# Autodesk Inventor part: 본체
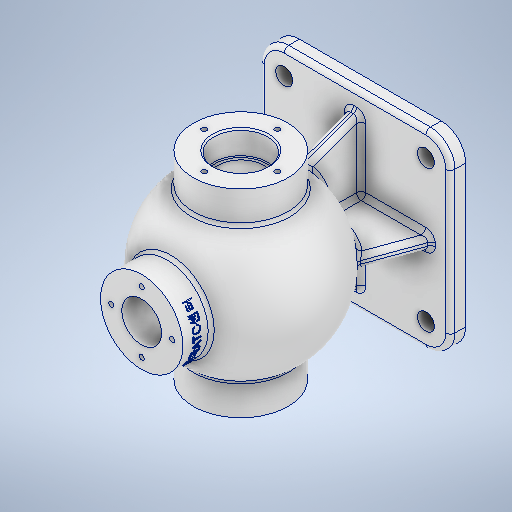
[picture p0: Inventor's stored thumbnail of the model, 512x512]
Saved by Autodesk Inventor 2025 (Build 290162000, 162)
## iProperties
Created: 2025-08
Part Number: 본체
Material: 알루미늄 6061
Document SubType Name: Modeling
Designer: infra028
Density: 2.7 g/cm^3
Appearance: 알루미늄 - 평지
Mass: 1526.56 g
Surface Area: 1173.66 cm^2
Volume: 565.392 cm^3
Author: infra028
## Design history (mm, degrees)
sketch "스케치1"
  geometry: L1 (-62.5, 62.5)-(62.5, 62.5); L2 (62.5, 62.5)-(62.5, -62.5); L3 (62.5, -62.5)-(-62.5, -62.5); L4 (-62.5, -62.5)-(-62.5, 62.5); L5 (-62.5, 62.5)-(62.5, -62.5); L6 (62.5, 62.5)-(-62.5, -62.5); 1 further point
  constraints: 12 end point, 2 midpoint, 2 parallel, 1 horizontal, 1 perpendicular
  dimensions: "d0" = 125 distance of L2.end L3.end; "d1" = 125 distance of L1.end L2.end
extrude "돌출1" new body sketch "스케치1" distance "d2" = 10; taper "d3" = 0 deg
sketch "스케치2"
  geometry: L1 (-46.5, 46.5)-(46.5, 46.5); L2 (46.5, 46.5)-(46.5, -46.5); L3 (46.5, -46.5)-(-46.5, -46.5); L4 (-46.5, -46.5)-(-46.5, 46.5); L5 (62.5, -62.5)-(62.5, 62.5) reference; L6 (-62.5, 62.5)-(-62.5, -62.5) reference; L7 (62.5, 62.5)-(-62.5, 62.5) reference; L8 (-62.5, -62.5)-(62.5, -62.5) reference; 5 further points
  constraints: 8 end point, 4 coincident, 2 parallel, 1 horizontal, 1 perpendicular
  dimensions: "d4" = 93 distance of L2.end L3.end; "d5" = 93 distance of L1.end L2.end; "d6" = 16 distance between parallel lines of L5 L2 (= d7); "d7" = 16 distance between parallel lines of L4 L6 (derived); "d8" = 16 distance between parallel lines of L1 L7 (= d9); "d9" = 16 distance between parallel lines of L8 L3 (derived)
hole "구멍1" sketch "스케치2" at (46.5, 46.5), (-46.5, -46.5), (46.5, -46.5), (-46.5, 46.5) diameter "d10" = 11; stored, may be unused: countersink angle "d14" = 90 deg, drill point angle "d16" = 0 deg; dims "d11" = 8, "d12" = 4, "d13" = 2, "d15" = 11.8
sketch "스케치4"
  geometry: L1 (54, 85)-(-54, 85); L2 (62.5, 0)-(-62.5, 0) reference; L3 (62.5, 0)-(62.5, 10) reference; A1 r 54 centre (0, 85) between (54, 85) and (-54, 85); 3 further points
  constraints: 2 end point, 2 midpoint, 2 point on circle, 1 centre point, 1 horizontal
  dimensions: "d18" = 108 diameter of A1; "d20" = 85 distance from line of L2 point (0, 85); "d21" = 62.5 horizontal distance of A1.centre point (62.5, 5); "d22" = 8.5 distance from line of L1.start L3
revolve "회전1" sketch "스케치4" stored, may be unused: angle "d19" = 360 deg
sketch "스케치5"
  geometry: L1 (-62.5, 10)-(62.5, 10) reference; L2 (-34.447, 54.104)-(-50.5, 10); L3 (43.084, 10)-(-50.5, 10); L4 (62.5, 0)-(62.5, 10) reference; L5 (-62.5, 0)-(-62.5, 10) reference; L6 (50.5, 10)-(34.447, 54.104); L7 (34.447, 54.104)-(-34.447, 54.104); 1 further point
  constraints: 8 end point, 3 point on line, 1 horizontal
  dimensions: "d24" = 20 deg angle of L2 L5; "d25" = 20 deg angle of L4 L6; "d26" = 12 distance from line of L6.start L4; "d27" = 12 distance of L1.start L2.end; "d28" = 44.10432 distance between parallel lines of L1 L7
extrude "돌출2" join sketch "스케치5" stored distance "d29" = 8; taper "d30" = 0 deg
sketch "스케치6"
  geometry: L1 (50.5, 10)-(33.738, 56.054); L2 (62.5, 0)-(62.5, 10) reference; L3 (-62.5, 10)-(62.5, 10) reference; L4 (-50.5, 10)-(-33.738, 56.054); L5 (-62.5, 0)-(-62.5, 10) reference; L6 (33.738, 56.054)-(-33.738, 56.054); 1 further point
  constraints: 6 end point, 2 point on line, 1 horizontal
  dimensions: "d31" = 20 deg angle of L2 L1; "d32" = 12 distance of L2.end L1.start; "d33" = 20 deg angle of L5 L4; "d34" = 12 distance of L3.start L4.start; "d35" = 46.0543 distance between parallel lines of L3 L6
extrude "돌출3" join sketch "스케치6" stored distance "d36" = 8; taper "d37" = 0 deg
sketch "스케치7"
  geometry: L1 (0, 85)-(-65, 85); L2 (-65, 85)-(-65, 116); L3 (-65, 116)-(-37.385, 116); L4 (-37.385, 116)-(-37.385, 85); 1 further point
  constraints: 8 end point, 2 horizontal, 2 perpendicular, 1 point on line
  dimensions: "d38" = 65 distance of L1.start L1.end; "d39" = 31 distance of L1.end L2.end; "d40" = 27.61518 distance between parallel lines of L4 L2; "d41" = 85 distance from line of point (0, 0) L1; "d42" = 37.38482 distance from line of point (0, 0) L4
revolve "회전2" sketch "스케치7" stored, may be unused: angle "d43" = 360 deg
sketch "스케치8"
  geometry: L1 (0, 85)-(0, 150); L2 (27, 150)-(-27, 150); L3 (27, 150)-(27, 124.409); L4 (27, 124.409)-(-27, 124.409); L5 (-27, 124.409)-(-27, 150); L6 (27, 137.204)-(-27, 137.204); A1 r 54 centre (0, 85) between (37.385, 46.034) and (-37.385, 46.034) reference; 5 further points
  constraints: 12 end point, 3 midpoint, 2 perpendicular, 2 vertical, 1 coincident, 1 horizontal
  dimensions: "d44" = 65 distance of L1.end L1.start; "d45" = 54 distance of L2.start L2.end; "d46" = 25.59142 distance between parallel lines of L4 L2
revolve "회전3" sketch "스케치8" stored, may be unused: angle "d47" = 360 deg
sketch "스케치9"
  geometry: L1 (65, 116)-(65, 54) reference; L2 (-65, 116)-(-65, 54) reference; L3 (65, 85)-(-65, 85); L4 (65, 102.5)-(49, 102.5); L5 (49, 102.5)-(49, 100); L6 (49, 100)-(41.364, 100); L7 (-65, 102.5)-(-49, 102.5); L8 (-49, 102.5)-(-49, 100); L9 (-49, 100)-(-41.364, 100); A1 r 54 centre (0, 85) between (37.385, 46.034) and (-37.385, 46.034) reference; A2 r 44 centre (0, 85) between (41.364, 100) and (-41.364, 100); 1 further point
  constraints: 14 end point, 5 perpendicular, 2 midpoint, 2 point on circle, 2 point on line, 1 centre point, 1 coincident, 1 horizontal
  dimensions: "d48" = 88 diameter of A2; "d49" = 17.5 distance between parallel lines of L3 L4; "d50" = 15 distance between parallel lines of L3 L6; "d51" = 16 distance between parallel lines of L1 L5; "d52" = 17.5 distance between parallel lines of L3 L7; "d53" = 15 distance between parallel lines of L3 L9; "d54" = 16 distance between parallel lines of L2 L8
revolve "회전4" sketch "스케치9" stored, may be unused: angle "d55" = 360 deg
sketch "스케치10"
  geometry: L1 (-41.364, 100)-(-41.364, 70) reference; L2 (41.364, 100)-(41.364, 70) reference; L3 (27, 150)-(-27, 150) reference; L4 (13, 150)-(13, 127.036); L5 (0, 150)-(0, 129); A1 r 44 centre (0, 85) between (41.364, 100) and (41.364, 70) reference; 1 further point
  constraints: 4 end point, 2 point on circle, 1 midpoint, 1 parallel, 1 perpendicular, 1 point on line
  dimensions: "d56" = 13 distance between parallel lines of L5 L4
revolve "회전5" sketch "스케치10" stored, may be unused: angle "d57" = 360 deg
sketch "스케치13"
  geometry: L1 (0, 0)-(0, -24); C1 r 17.5 at (0, 0) reference; 5 further points
  constraints: 2 end point, 1 coincident, 1 vertical, 5 other
  dimensions: "d58" = 24 distance of L1.start L1.end; "d61" = 360 deg dimension on L1.start point (0, -24) (derived)
hole "구멍2" sketch "스케치13" at (0, -24), (24, 0), (0, 24), (-24, 0) diameter "d63" = 3.242; stored, may be unused: countersink angle "d67" = 90 deg, drill point angle "d69" = 118 deg; dims "d64" = 12, "d65" = 4, "d66" = 2, "d68" = 15
sketch "스케치14"
  geometry: L1 (0, 0)-(0, 20); 4 further points
  constraints: 2 end point, 1 coincident, 1 vertical, 5 other
  dimensions: "d70" = 20 distance of L1.start L1.end; "d73" = 360 deg dimension on L1.start point (0, 20) (derived)
hole "구멍3" sketch "스케치14" at (0, 20), (-20, 0), (0, -20), (20, 0) diameter "d75" = 3.242; stored, may be unused: countersink angle "d79" = 90 deg, drill point angle "d81" = 118 deg; dims "d76" = 9, "d77" = 4, "d78" = 2, "d80" = 11
fillet "모깎기1" dims "d82" = 16
fillet "모깎기2" dims "d83" = 3
fillet "모깎기3" dims "d84" = 3
fillet "모깎기4" dims "d85" = 3
fillet "모깎기5" dims "d86" = 3
fillet "모깎기6" dims "d87" = 3
chamfer "모따기1" distance "d88" = 1; stored, may be unused: second distance "d89" = 2, angle "d90" = 45 deg
chamfer "모따기3" distance "d94" = 1; stored, may be unused: second distance "d95" = 2, angle "d96" = 45 deg
node "작업 평면3"
sketch "스케치17"
  geometry: L1 (-15.721, 8.433)-(15.721, 8.433); L2 (15.721, 8.433)-(15.721, -0.842); L3 (15.721, -0.842)-(-15.721, -0.842); L4 (-15.721, -0.842)-(-15.721, 8.433); L5 (27, 12.796)-(-27, 12.796) reference; L6 (-46.5, -137.204)-(46.5, -137.204) reference; 5 further points
  constraints: 4 midpoint, 1 vertical alignment, 2 other
  dimensions: "d102" = 9 distance from line of point (-15.721, 3.796) L5
feature "엠보싱1" sketch "스케치17" dims "d0" = 125, "d1" = 125, "d103" = 0.5, "d104" = 0
fillet "모깎기7" dims "d105" = 0.6
fillet "모깎기8" dims "d106" = 0.6
feature "І耀Ј耀Њ耀Ќ耀Ў耀А耀В耀Д耀" dims "d0" = 125, "d1" = 125, "d2" = 10, "d3" = 0, "d4" = 93, "d5" = 93, "d6" = 16 (= d7), "d7" = 16 (derived), "d8" = 16 (= d9), "d9" = 16 (derived), "d10" = 11, "d11" = 8, "d12" = 4, "d13" = 2, "d14" = 90 deg, "d15" = 11.8, "d16" = 0, "d18" = 108, "d19" = 360 deg, "d20" = 85, "d21" = 62.5, "d22" = 8.5, "d24" = 20 deg, "d25" = 20 deg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
node "솔리드1"
mirror "미러1"
mirror "미러3"
node "작업 평면1"
node "투영된 루프1"
node "스케치 - 원형 패턴1" dims "d61" = 360 deg (derived)
node "스케치 - 원형 패턴2" dims "d73" = 360 deg (derived)
feature "A9D066F2-1C7D-4E18-AEED-F7BC21143FA4" dims "d10" = 11, "d11" = 8, "d12" = 4, "d13" = 2, "d14" = 90 deg, "d15" = 11.8, "d16" = 0
